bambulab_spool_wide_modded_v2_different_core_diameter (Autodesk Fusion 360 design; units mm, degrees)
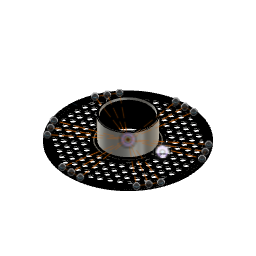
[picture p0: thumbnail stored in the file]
parameter "lattice_diameter" = 10.25
parameter "lattice_thickness" = 3.75
parameter "hole_diameter" = 3.5 comment "Hole Diameter of the rim"
parameter "center_core_outer_diameter" = 74 comment "The outer diameter the core should have, must be between 69 and 80 (inclusive)"
base_mesh_feature "Base Mesh Feature"
convert_mesh "Convert Mesh" bodies "bambulab_spool_wide"
sketch "Sketch13" plane through (0, 0, -16.75) normal (0, 0, 1) x axis (-1, 0, 0)
  line L1 (92.6217, -5.7502) -> (99.4206, -5.9753)
  line L2 (92.483, -7.6633) -> (92.6217, -5.7502)
  line L3 (99.4206, -5.9753) -> (92.483, -7.6633)
  line L4 (0, 0) -> (-74.6153, -60.4003)
  line L5 (-89.6135, -34.4171) -> (0, 0)
  line L6 (-74.6153, -60.4003) -> (-89.6135, -34.4171)
  line L7 (-15.0006, -94.8162) -> (0, 0)
  line L8 (15.0006, -94.8189) -> (-15.0006, -94.8162)
  line L9 (0, 0) -> (15.0006, -94.8189)
  line L10 (0, 0) -> (74.6129, -60.399)
  line L11 (0, 0) -> (89.6159, -34.4185)
  line L12 (74.6129, -60.399) -> (89.6159, -34.4185)
  line L13 (89.6135, 34.4171) -> (0, 0)
  line L14 (74.6153, 60.4003) -> (89.6135, 34.4171)
  line L15 (0, 0) -> (74.6153, 60.4003)
  line L16 (0, 0) -> (-15.0006, 94.8189)
  line L17 (15.0006, 94.8162) -> (-15.0006, 94.8189)
  line L18 (0, 0) -> (15.0006, 94.8162)
  line L19 (0, 0) -> (-89.6159, 34.4185)
  line L20 (-89.6159, 34.4185) -> (-74.6129, 60.399)
  line L21 (0, 0) -> (-74.6129, 60.399)
  line L22 (0, 0) -> (-82.1144, 47.4088)
  line L23 (0, 0) -> (0, 94.8175)
  line L24 (0, 0) -> (82.1144, 47.4087)
  line L25 (0, 0) -> (82.1144, -47.4088)
  line L26 (0, 0) -> (0, -94.8175)
  line L27 (0, 0) -> (-82.1144, -47.4087)
  circle C1 centre (15.0006, -94.8189) radius 2
  circle C2 centre (-15.0006, -94.8162) radius 2
  circle C3 centre (89.6159, -34.4185) radius 2
  circle C4 centre (74.6153, 60.4003) radius 2
  circle C5 centre (-15.0006, 94.8189) radius 2
  circle C6 centre (-89.6159, 34.4185) radius 2
  circle C7 centre (-74.6153, -60.4003) radius 2
  circle C8 centre (74.6129, -60.399) radius 2
  circle C9 centre (89.6135, 34.4171) radius 2
  circle C10 centre (15.0006, 94.8162) radius 2
  circle C11 centre (-74.6129, 60.399) radius 2
  circle C12 centre (-89.6135, -34.4171) radius 2
  point P1 (0, 0)
  point P7 (0, 0)
  point P12 (-74.6153, -60.4003)
  point P18 (-74.6153, -60.4003)
  point P19 (0, 0)
  point P17 (-89.6135, -34.4171)
  point P20 (-89.6135, -34.4171)
  point P21 (-74.6153, -60.4003)
  point P22 (-82.1144, -47.4087)
  point P23 (0, 0)
  point P6 (-15.0006, -94.8162)
  point P24 (-15.0006, -94.8162)
  point P5 (15.0006, -94.8189)
  point P25 (15.0006, -94.8189)
  point P26 (0, 0)
  point P13 (74.6129, -60.399)
  point P27 (74.6129, -60.399)
  point P28 (0, 0)
  point P8 (89.6159, -34.4185)
  point P29 (89.6159, -34.4185)
  point P30 (0, 0)
  point P31 (89.6159, -34.4185)
  point P14 (89.6135, 34.4171)
  point P32 (89.6135, 34.4171)
  point P9 (74.6153, 60.4003)
  point P33 (74.6153, 60.4003)
  point P34 (0, 0)
  point P10 (-15.0006, 94.8189)
  point P35 (-15.0006, 94.8189)
  point P36 (0, 0)
  point P37 (-15.0006, 94.8189)
  point P15 (15.0006, 94.8162)
  point P38 (15.0006, 94.8162)
  point P39 (15.0006, 94.8162)
  point P40 (0, 0)
  point P11 (-89.6159, 34.4185)
  point P41 (-89.6159, 34.4185)
  point P42 (0, 0)
  point P16 (-74.6129, 60.399)
  point P43 (-74.6129, 60.399)
  point P44 (-89.6159, 34.4185)
  point P45 (0, -94.8175)
  point P46 (82.1144, -47.4088)
  point P47 (82.1144, 47.4087)
  point P48 (0, 94.8175)
  point P49 (-82.1144, 47.4088)
  point P50 (-82.1144, 47.4088)
  point P51 (0, 0)
  point P52 (0, 94.8175)
  point P53 (0, 0)
  point P54 (82.1144, 47.4087)
  point P55 (82.1144, -47.4088)
  point P56 (0, -94.8175)
  point P57 (-82.1144, -47.4087)
  point P58 (0, 0)
  coincident P1 P7
  coincident P12 P18
  coincident P7 P19
  coincident P17 P20
  coincident P12 P21
  midpoint L6 P22
  coincident P7 P23
  coincident P6 P24
  coincident P5 P25
  coincident P1 P26
  coincident P13 P27
  coincident P1 P28
  coincident P8 P29
  coincident P7 P30
  coincident P8 P31
  coincident P14 P32
  coincident P9 P33
  coincident P1 P34
  coincident P10 P35
  coincident P1 P36
  coincident P10 P37
  coincident P15 P38
  coincident P15 P39
  coincident P1 P40
  coincident P11 P41
  coincident P7 P42
  coincident P16 P43
  coincident P11 P44
  midpoint L8 P45
  midpoint L12 P46
  midpoint L14 P47
  midpoint L17 P48
  midpoint L20 P49
  coincident P49 P50
  coincident P1 P51
  coincident P48 P52
  coincident P7 P53
  coincident P47 P54
  coincident P46 P55
  coincident P45 P56
  coincident P22 P57
  coincident P1 P58
  dimension "d48" diameter C1 = 4
  dimension "d49" diameter C2 = 4
  dimension "d51" C-Pattern1-Angle = 360
  dimension "d53" C-Pattern2-Angle = 360
extrude "Extrude5" cut sketch "Sketch13" profile of C3 C4 C6 C7 C8 C9 C11 C12 against normal blind 25
sketch "Sketch14" plane through (0, 0, -17.85) normal (0, 0, 1) x axis (-1, 0, 0)
  line L1 (-23.297, 37.7968) -> (-24.4167, 37.0834)
  line L2 (-2.5625, 4.4384) -> (2.5625, 4.4384)
  line L3 (-5.125, 0) -> (-2.5625, 4.4384)
  line L4 (-2.5625, -4.4384) -> (-5.125, 0)
  line L5 (2.5625, -4.4384) -> (-2.5625, -4.4384)
  line L6 (5.125, 0) -> (2.5625, -4.4384)
  line L7 (2.5625, 4.4384) -> (5.125, 0)
  line L8 (5.125, -12.6268) -> (2.5625, -17.0651)
  line L9 (2.5625, -8.1884) -> (5.125, -12.6268)
  line L10 (-2.5625, -8.1884) -> (2.5625, -8.1884)
  line L11 (-5.125, -12.6268) -> (-2.5625, -8.1884)
  line L12 (-2.5625, -17.0651) -> (-5.125, -12.6268)
  line L13 (2.5625, -17.0651) -> (-2.5625, -17.0651)
  line L14 (0, -45.5) -> (0, 45.5)
  line L15 (-37, 0) -> (37, 0)
  line L16 (16.0601, -6.3134) -> (13.4976, -10.7518)
  line L17 (13.4976, -1.875) -> (16.0601, -6.3134)
  line L18 (8.3726, -1.875) -> (13.4976, -1.875)
  line L19 (5.8101, -6.3134) -> (8.3726, -1.875)
  line L20 (8.3726, -10.7518) -> (5.8101, -6.3134)
  line L21 (13.4976, -10.7518) -> (8.3726, -10.7518)
  line L22 (13.4976, 10.7518) -> (16.0601, 6.3134)
  line L23 (8.3726, 10.7518) -> (13.4976, 10.7518)
  line L24 (5.8101, 6.3134) -> (8.3726, 10.7518)
  line L25 (8.3726, 1.875) -> (5.8101, 6.3134)
  line L26 (13.4976, 1.875) -> (8.3726, 1.875)
  line L27 (16.0601, 6.3134) -> (13.4976, 1.875)
  line L28 (-5.125, -17.0651) -> (-5.125, 10.7518)
  line L29 (16.0601, -17.0651) -> (16.0601, 10.7518)
  line L30 (-5.125, 10.7518) -> (16.0601, 10.7518)
  line L31 (-5.125, -17.0651) -> (16.0601, -17.0651)
  line L32 (-92.4279, -85.5158) -> (-89.8654, -89.9542)
  line L33 (-89.8654, -89.9542) -> (-92.4279, -94.3926)
  line L34 (-92.4279, -94.3926) -> (-97.5529, -94.3926)
  line L35 (-97.5529, -94.3926) -> (-100.1154, -89.9542)
  line L36 (-100.1154, -89.9542) -> (-97.5529, -85.5158)
  line L37 (-97.5529, -85.5158) -> (-92.4279, -85.5158)
  line L38 (-92.4279, -98.1426) -> (-89.8654, -102.581)
  line L39 (-97.5529, -98.1426) -> (-92.4279, -98.1426)
  line L40 (-100.1154, -102.581) -> (-97.5529, -98.1426)
  line L41 (-97.5529, -107.0194) -> (-100.1154, -102.581)
  line L42 (-92.4279, -107.0194) -> (-97.5529, -107.0194)
  line L43 (-89.8654, -102.581) -> (-92.4279, -107.0194)
  line L44 (-100.8005, -96.2676) -> (-103.363, -100.706)
  line L45 (-103.363, -91.8292) -> (-100.8005, -96.2676)
  line L46 (-108.488, -91.8292) -> (-103.363, -91.8292)
  line L47 (-111.0505, -96.2676) -> (-108.488, -91.8292)
  line L48 (-108.488, -100.706) -> (-111.0505, -96.2676)
  line L49 (-103.363, -100.706) -> (-108.488, -100.706)
  line L50 (-108.488, -104.456) -> (-103.363, -104.456)
  line L51 (-103.363, -104.456) -> (-100.8005, -108.8944)
  line L52 (-100.8005, -108.8944) -> (-103.363, -113.3327)
  line L53 (-103.363, -113.3327) -> (-108.488, -113.3327)
  line L54 (-108.488, -113.3327) -> (-111.0505, -108.8944)
  line L55 (-111.0505, -108.8944) -> (-108.488, -104.456)
  line L56 (-71.2428, -85.5158) -> (-68.6803, -89.9542)
  line L57 (-68.6803, -89.9542) -> (-71.2428, -94.3926)
  line L58 (-71.2428, -94.3926) -> (-76.3678, -94.3926)
  line L59 (-76.3678, -94.3926) -> (-78.9303, -89.9542)
  line L60 (-78.9303, -89.9542) -> (-76.3678, -85.5158)
  line L61 (-76.3678, -85.5158) -> (-71.2428, -85.5158)
  line L62 (-71.2428, -98.1426) -> (-68.6803, -102.581)
  line L63 (-76.3678, -98.1426) -> (-71.2428, -98.1426)
  line L64 (-78.9303, -102.581) -> (-76.3678, -98.1426)
  line L65 (-76.3678, -107.0194) -> (-78.9303, -102.581)
  line L66 (-71.2428, -107.0194) -> (-76.3678, -107.0194)
  line L67 (-68.6803, -102.581) -> (-71.2428, -107.0194)
  line L68 (-79.6154, -96.2676) -> (-82.1779, -100.706)
  line L69 (-82.1779, -91.8292) -> (-79.6154, -96.2676)
  line L70 (-87.3029, -91.8292) -> (-82.1779, -91.8292)
  line L71 (-89.8654, -96.2676) -> (-87.3029, -91.8292)
  line L72 (-87.3029, -100.706) -> (-89.8654, -96.2676)
  line L73 (-82.1779, -100.706) -> (-87.3029, -100.706)
  line L74 (-87.3029, -104.456) -> (-82.1779, -104.456)
  line L75 (-82.1779, -104.456) -> (-79.6154, -108.8944)
  line L76 (-79.6154, -108.8944) -> (-82.1779, -113.3327)
  line L77 (-82.1779, -113.3327) -> (-87.3029, -113.3327)
  line L78 (-87.3029, -113.3327) -> (-89.8654, -108.8944)
  line L79 (-89.8654, -108.8944) -> (-87.3029, -104.456)
  line L80 (-50.0577, -85.5158) -> (-47.4952, -89.9542)
  line L81 (-47.4952, -89.9542) -> (-50.0577, -94.3926)
  line L82 (-50.0577, -94.3926) -> (-55.1827, -94.3926)
  line L83 (-55.1827, -94.3926) -> (-57.7452, -89.9542)
  line L84 (-57.7452, -89.9542) -> (-55.1827, -85.5158)
  line L85 (-55.1827, -85.5158) -> (-50.0577, -85.5158)
  line L86 (-50.0577, -98.1426) -> (-47.4952, -102.581)
  line L87 (-55.1827, -98.1426) -> (-50.0577, -98.1426)
  line L88 (-57.7452, -102.581) -> (-55.1827, -98.1426)
  line L89 (-55.1827, -107.0194) -> (-57.7452, -102.581)
  line L90 (-50.0577, -107.0194) -> (-55.1827, -107.0194)
  line L91 (-47.4952, -102.581) -> (-50.0577, -107.0194)
  line L92 (-58.4303, -96.2676) -> (-60.9928, -100.706)
  line L93 (-60.9928, -91.8292) -> (-58.4303, -96.2676)
  line L94 (-66.1178, -91.8292) -> (-60.9928, -91.8292)
  line L95 (-68.6803, -96.2676) -> (-66.1178, -91.8292)
  line L96 (-66.1178, -100.706) -> (-68.6803, -96.2676)
  line L97 (-60.9928, -100.706) -> (-66.1178, -100.706)
  line L98 (-66.1178, -104.456) -> (-60.9928, -104.456)
  line L99 (-60.9928, -104.456) -> (-58.4303, -108.8944)
  line L100 (-58.4303, -108.8944) -> (-60.9928, -113.3327)
  line L101 (-60.9928, -113.3327) -> (-66.1178, -113.3327)
  line L102 (-66.1178, -113.3327) -> (-68.6803, -108.8944)
  line L103 (-68.6803, -108.8944) -> (-66.1178, -104.456)
  line L104 (-28.8726, -85.5158) -> (-26.3101, -89.9542)
  line L105 (-26.3101, -89.9542) -> (-28.8726, -94.3926)
  line L106 (-28.8726, -94.3926) -> (-33.9976, -94.3926)
  line L107 (-33.9976, -94.3926) -> (-36.5601, -89.9542)
  line L108 (-36.5601, -89.9542) -> (-33.9976, -85.5158)
  line L109 (-33.9976, -85.5158) -> (-28.8726, -85.5158)
  line L110 (-28.8726, -98.1426) -> (-26.3101, -102.581)
  line L111 (-33.9976, -98.1426) -> (-28.8726, -98.1426)
  line L112 (-36.5601, -102.581) -> (-33.9976, -98.1426)
  line L113 (-33.9976, -107.0194) -> (-36.5601, -102.581)
  line L114 (-28.8726, -107.0194) -> (-33.9976, -107.0194)
  line L115 (-26.3101, -102.581) -> (-28.8726, -107.0194)
  line L116 (-37.2452, -96.2676) -> (-39.8077, -100.706)
  line L117 (-39.8077, -91.8292) -> (-37.2452, -96.2676)
  line L118 (-44.9327, -91.8292) -> (-39.8077, -91.8292)
  line L119 (-47.4952, -96.2676) -> (-44.9327, -91.8292)
  line L120 (-44.9327, -100.706) -> (-47.4952, -96.2676)
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  point P1 (0, 0)
  point P4 (0, 0)
  point P5 (0, 0)
  point P6 (0, 0)
  point P13 (0, 0)
  point P20 (0, -12.6268)
  point P9 (-5.125, 0)
  point P26 (16.0601, -6.3134)
  point P41 (16.0601, -17.0651)
  point P42 (-5.125, -17.0651)
  point P39 (-5.125, 10.7518)
  point P40 (16.0601, 10.7518)
  point P12 (5.125, 0)
  point P7 (2.5625, 4.4384)
  point P10 (-2.5625, -4.4384)
  point P15 (5.125, -12.6268)
  point P18 (-5.125, -12.6268)
  point P14 (2.5625, -17.0651)
  point P17 (-2.5625, -8.1884)
  point P29 (5.8101, -6.3134)
  point P32 (16.0601, 6.3134)
  point P35 (5.8101, 6.3134)
  coincident P1 P4
  coincident P1 P5
  coincident P1 P6
  coincident P5 P13
  vertical L14
  horizontal L15
  coincident P1 L14
  midpoint P4 L15
  midpoint P1 L14
  coincident P20 L14
  parallel L5 L15
  parallel L15 L21
  parallel L15 L26
  vertical L28
  vertical L29
  coincident P9 L28
  coincident P26 L29
  perpendicular L29 L30
  horizontal L31
  collinear L23 L30
  collinear L13 L31
  coincident L29 P41
  coincident L28 P42
  coincident P39 L30
  coincident L29 P40
  dimension "d56" diameter = 183.4
  dimension "d57" diameter = 89
  dimension "d62" diameter = 179.65 (= "183.4 mm - lattice_thickness")
  dimension "d63" distance P9 P12 = 10.25 (= "lattice_diameter")
  dimension "d64" distance P7 P10 = 10.25 (= "lattice_diameter")
  dimension "d65" distance P15 P18 = 10.25 (= "lattice_diameter")
  dimension "d66" distance P14 P17 = 10.25 (= "lattice_diameter")
  dimension "d67" distance L5 L10 = 3.75 (= "lattice_thickness")
  dimension "d68" distance P26 P29 = 10.25 (= "lattice_diameter")
  dimension "d69" distance L6 L19 = 3.75 (= "lattice_thickness")
  dimension "d70" distance L9 L20 = 3.75 (= "lattice_thickness")
  dimension "d71" distance P32 P35 = 10.25 (= "lattice_diameter")
  dimension "d72" distance L18 L26 = 3.75 (= "lattice_thickness")
  dimension "d73" distance L7 L25 = 3.75 (= "lattice_thickness")
  dimension "d74" distance P41 P42 = 21.1851
  dimension "d75" distance P40 P41 = 27.8169
  dimension "d78" R-Pattern1-uDistance = 21.1851
  dimension "d79" R-Pattern1-vDistance = 24.0669 (= "27.816899 mm - lattice_thickness")
extrude "Extrude6" cut sketch "Sketch14" distance 30
work_plane "WorkPlane3" RotateAngle 45
sketch "Sketch16" plane through (27.1973, 30.4798, 1.2) normal (0.7071, 0.7071, -0.0003) x axis (-0.0041, 0.0036, -1)
  line L1 (17.7883, -26.5886) -> (17.7779, -28.5173)
  circle C1 centre (17.5808, -27.9755) radius 1.1
  point P2 (17.5808, -27.9755)
  dimension "d84" diameter C1 = 2.2
  dimension "d85" distance P2 L1 = 0.2
extrude "Extrude7" cut sketch "Sketch16" profile of C1 against normal blind 13
work_plane "WorkPlane4" RotateAngle 120
sketch "Sketch17" plane through (37.7529, -15.5941, 1.2) normal (0.6096, -0.7926, -0.0143) x axis (0.0109, 0.0265, -0.9996)
  line L1 (19.3005, 6.8332) -> (19.2658, 5.9127)
  circle C1 centre (17.9921, 7.9641) radius 1.1
  point P2 (17.9921, 7.9641)
  dimension "d89" diameter C1 = 2.2
  dimension "d93" distance P2 L1 = 1.35
extrude "Extrude8" cut sketch "Sketch17" profile of C1 against normal blind 10.5
sketch "Sketch18" plane through (0, 0, -17.85) normal (0, 0, 1) x axis (-1, 0, 0)
  line L1 (-48.5558, 4.4764) -> (-47.9524, 5.5214)
  line L2 (-40.6099, 4.4226) -> (-48.5558, 4.4764)
  line L3 (-40.4572, 5.6509) -> (-40.6099, 4.4226)
  line L4 (-47.9524, 5.5214) -> (-40.4572, 5.6509)
  line L5 (-44, 2.7549) -> (-40.755, 2.7549)
  line L6 (-44, -2.9962) -> (-44, 2.7549)
  line L7 (-40.738, -2.9962) -> (-44, -2.9962)
  circle C1 centre (0, 0) radius 40.848
  point P1 (0, 0)
  point P6 (0, 0)
  point P7 (-40.755, 2.7549)
  point P10 (-40.738, -2.9962)
  coincident P1 P6
  coincident C1 P7
  horizontal L5
  perpendicular L5 L6
  coincident C1 P10
  perpendicular L6 L7
  dimension "d94" diameter C1 = 81.696
extrude "Extrude9" cut sketch "Sketch18" profile of C1 L5 L6 L7 along normal blind 9
sketch "Sketch19" plane through (7.5003, 47.4081, -16.75) normal (-0.6984, 0.1105, 0.7071) x axis (0.1563, 0.9877, 0)
  circle C1 centre (48, 0) radius 1.75
  dimension "d101" diameter C1 = 3.5 (= "hole_diameter")
extrude "Extrude11" add sketch "Sketch13" profile of C1 C2 C5 C10 against normal blind 3.6
work_plane "WorkPlane8" RotateAngle 45
sketch "Sketch20" plane through (44.8068, 17.2086, -16.75) normal (0.2535, -0.6601, 0.7071) x axis (0.9335, 0.3585, 0)
  circle C1 centre (48, 0) radius 1.75
  dimension "d107" diameter C1 = 3.5 (= "hole_diameter")
extrude "Extrude12" new body sketch "Sketch20" distance 20
work_plane "WorkPlane9" RotateAngle 45
sketch "Sketch22" plane through (37.3076, 30.2002, -16.75) normal (-0.4449, 0.5496, 0.7071) x axis (-0.7773, -0.6292, 0)
  circle C1 centre (-48, 0) radius 1.75
  dimension "d111" diameter C1 = 3.5 (= "hole_diameter")
extrude "Extrude13" new body sketch "Sketch22" distance 20
circular_pattern "C-Pattern1" TotalAngle 360
combine "Combine1"
sketch "Outer Wall Change" plane through (0, 0, 0) normal (1, 0, 0) x axis (0, 1, 0)
  line L1 (41.3481, -17.35) -> (41.3524, -17.35)
  line L2 (41.2434, -17.2442) -> (41.3481, -17.35)
  line L3 (39.75, 20.35) -> (40.8451, 19.25)
  line L4 (39, 20.35) -> (39.75, 20.35)
  line L5 (39, 5.35) -> (39, 20.35)
  line L6 (38.9954, 5.35) -> (39, 5.35)
  line L7 (33.3, 16.4) -> (33.3, 5.35)
  line L8 (40.8453, -16.85) -> (41.3481, -17.35)
  line L9 (40.8453, -16.85) -> (40.8451, 19.25)
  line L10 (39, 5.35) -> (33.3, 5.35)
  line L11 (35.9049, 20.35) -> (35.1549, 20.35)
  line L12 (39.75, 20.35) -> (35.9049, 20.35)
  line L13 (39, 20.35) -> (35.1549, 20.35)
  line L14 (37, 19.25) -> (35.9049, 20.35)
  line L15 (40.8451, 19.25) -> (37, 19.25)
  line L16 (37.0002, -16.85) -> (37, 19.25)
  line L17 (35.1549, 20.35) -> (35.1549, -17.35)
  line L18 (37.5031, -17.35) -> (37.0002, -16.85)
  line L19 (35.1549, -17.35) -> (37.5031, -17.35)
  line L20 (40.8452, 5.35) -> (39, 5.35)
  line L21 (40.8453, -16.85) -> (37.0002, -16.85)
  line L22 (41.3481, -17.35) -> (37.5031, -17.35)
  line L23 (42.5583, -17.35) -> (42.2154, -17.35)
  line L24 (35.1549, 34.6418) -> (35.1549, 20.35)
  line L25 (55.1549, 34.6418) -> (35.1549, 34.6418)
  line L26 (55.1549, -17.35) -> (55.1549, 34.6418)
  line L27 (41.3524, -17.35) -> (55.1549, -17.35)
  line L28 (43.1287, -17.35) -> (42.8629, -17.35)
  line L29 (37.5031, -17.65) -> (37.5031, -17.35)
  line L30 (38.9954, -17.65) -> (33.2946, -17.65)
  line L31 (39, -17.35) -> (37.5031, -17.35)
  line L32 (43.1287, -17.65) -> (38.9954, -17.65)
  line L33 (43.1287, -17.35) -> (43.1287, -17.65)
  line L34 (43.1287, -17.35) -> (41.3481, -17.35)
  line L35 (35.1549, -17.65) -> (35.1549, -17.35)
  line L36 (0, -25.35) -> (0, 0)
  line L37 (28.3, -25.35) -> (0, -25.35)
  line L38 (28.3, -20.35) -> (28.3, -25.35)
  line L39 (28.3, -20.35) -> (27.5, -19.55)
  line L40 (0, 0) -> (27.4676, 0)
  line L41 (27.5, -16.65) -> (27.4676, 0)
  line L42 (27.5, -19.55) -> (27.5, -16.65)
  point P3 (41.3481, -17.35)
  point P12 (41.3481, -17.35)
  point P5 (40.8451, 19.25)
  point P14 (40.8451, 19.25)
  point P10 (33.3, 5.35)
  point P15 (33.3, 5.35)
  point P8 (39, 5.35)
  point P16 (39, 5.35)
  point P6 (39.75, 20.35)
  point P19 (39.75, 20.35)
  point P7 (39, 20.35)
  point P20 (39, 20.35)
  point P22 (40.8451, 19.25)
  point P17 (35.1549, 20.35)
  point P23 (35.1549, 20.35)
  point P27 (39, 5.35)
  point P28 (40.8452, 5.35)
  point P31 (40.8428, -16.85)
  point P2 (41.3524, -17.35)
  point P35 (41.3524, -17.35)
  point P38 (37.5031, -17.65)
  point P41 (39, -17.35)
  point P40 (38.9954, -17.65)
  point P42 (38.9954, -17.65)
  point P37 (43.1287, -17.35)
  point P44 (43.1287, -17.35)
  point P45 (35.1549, -17.65)
  point P1 (0, 0)
  point P48 (0, 0)
  point P47 (28.3, -20.35)
  point P51 (28.3, -20.35)
  point P46 (27.5, -19.55)
  point P53 (27.5, -19.55)
  point P55 (0, 0)
  point P56 (27.5, -16.65)
  point P57 (27.5, -16.65)
  point P58 (27.5, -19.55)
  point P21 (37, 19.25)
  point P32 (35.1549, 34.6418)
  point P33 (55.1549, 34.6418)
  point P50 (28.3, -25.35)
  coincident P3 P12
  coincident P5 P14
  coincident P10 P15
  coincident P8 P16
  horizontal L11
  coincident P6 P19
  coincident P7 P20
  equal L12 L13
  coincident P5 P22
  equal L13 L15
  coincident P17 P23
  coincident P8 P27
  coincident L9 P28
  collinear L10 L20
  equal L21 L22
  equal L15 L21
  collinear L19 L23
  collinear L4 L11
  horizontal L15
  vertical L17
  horizontal L21
  coincident L21 P31
  perpendicular L11 L24
  perpendicular L24 L25
  coincident P2 P35
  collinear L27 L28
  perpendicular L25 L26
  perpendicular L19 L29
  coincident P38 L30
  coincident L22 P41
  coincident P40 P42
  parallel L30 L32
  coincident P37 P44
  vertical L33
  coincident L30 P45
  perpendicular L30 L35
  coincident P1 P48
  vertical L36
  perpendicular L36 L37
  coincident P47 P51
  vertical L38
  coincident P46 P53
  coincident P1 P55
  horizontal L40
  coincident P56 P57
  coincident P46 P58
  dimension "d116" distance P1 P21 = 37 (= "center_core_outer_diameter / 2")
  dimension "d118" distance P32 P33 = 20
  dimension "d121" distance P50 P51 = 5
revolve "Revolve2" sketch "Outer Wall Change" AlongAngle 360 bodies "Center Core Cut Outer Wall"
revolve "Revolve3" sketch "Outer Wall Change" AlongAngle 360 bodies "Center Core New Outer Wall"
combine "Combine2" bodies "Center Core Cut Outer Wall"
combine "Combine3" bodies "Center Core New Outer Wall"
named bodies: "bambulab_spool_wide", "Center Core Cut Outer Wall", "Center Core New Outer Wall"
